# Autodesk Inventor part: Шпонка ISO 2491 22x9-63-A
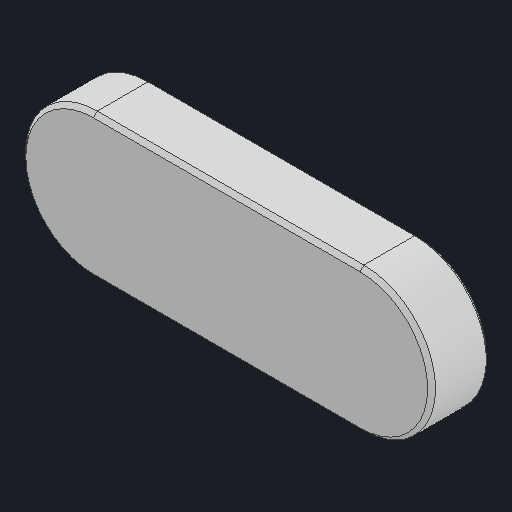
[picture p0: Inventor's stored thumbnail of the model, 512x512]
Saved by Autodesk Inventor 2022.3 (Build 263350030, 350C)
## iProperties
Created: 2020-09
Part Number: Шпонка ISO 2491 22x9-63-A
Material: Типовые
Description: Шпонка ISO 2491 22x9-63-A
Document SubType Name: Modeling
Designer: Карташов
Density: 1 g/cm^3
Appearance: По умолчанию
Title: D:\мои документы\Ирина\_WorldSkills\2020_09 ФНЧ\Module A\Участникам\GIVEN\Шпонка ISO 2491 22x9-63-A.stp
Author: Дом
Sending System: Autodesk Inventor 2021
Preprocessor: ST-DEVELOPER v18.1
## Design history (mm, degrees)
feature "Твердое тело2"
node "Твердое тело1"
